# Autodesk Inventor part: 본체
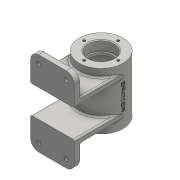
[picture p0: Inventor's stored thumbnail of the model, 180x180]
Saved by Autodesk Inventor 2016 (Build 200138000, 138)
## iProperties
Created: 2017-02
Part Number: 본체
Material: 일반
Document SubType Name: Modeling
Designer: CAMTIC
Density: 1 g/cm^3
Appearance: 기본값
Author: CAMTIC
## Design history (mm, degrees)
sketch "스케치1"
  geometry: L1 (27, 52)-(-27, 52); L2 (-27, -52)-(27, -52); L3 (27, -17)-(-27, -17); L4 (27, 17)-(-27, 17); L5 (-27, 52)-(-27, 17); L6 (-27, -17)-(-27, -52); L7 (27, -52)-(27, -17); L8 (27, 17)-(27, 52); 1 further point
  constraints: 16 end point, 5 parallel, 2 perpendicular, 1 horizontal
  dimensions: "d0" = 54 distance of L2.start L2.end; "d1" = 104 distance of L1.end L2.start
extrude "돌출1" new body sketch "스케치1" distance "d4" = 8; taper "d5" = 0 deg
sketch "스케치2"
  geometry: L1 (0, 0)-(0, 60); C1 r 27 at (0, 60)
  constraints: 2 end point, 1 centre point, 1 coincident, 1 vertical
  dimensions: "d6" = 60 distance of L1.start L1.end; "d7" = 54 diameter of C1
extrude "돌출2" join sketch "스케치2" stored distance "d8" = 70; taper "d9" = 0 deg
sketch "스케치3"
  geometry: L1 (0, 0)-(60, 0); L2 (33, -35)-(87, -35) reference; L3 (60, -35)-(60, 35); L4 (60, -35)-(76, -35); L5 (76, -35)-(76, -23); L6 (76, -23)-(74, -23); L7 (74, -23)-(74, -20); L8 (74, -20)-(82, -20); L9 (87, -35)-(87, 35) reference; L10 (82, -20)-(82, 20); L11 (82, 20)-(74, 20); L12 (74, 20)-(74, 23); L13 (74, 23)-(76, 23); L14 (76, 23)-(76, 35); L15 (87, 35)-(33, 35) reference; L16 (76, 35)-(60, 35)
  constraints: 26 end point, 6 perpendicular, 3 horizontal, 2 point on line, 2 vertical, 1 collinear, 1 midpoint
  dimensions: "d10" = 60 distance of L1.start L1.end; "d11" = 16 distance of L3.start L4.end; "d12" = 12 distance of L4.end L5.end; "d13" = 2 distance of L5.end L6.end; "d14" = 3 distance of L6.end L7.end; "d15" = 8 distance of L7.end L8.end; "d16" = 40 distance of L8.end L10.end; "d17" = 8 distance of L10.end L11.end; "d18" = 3 distance of L11.end L12.end; "d19" = 2 distance of L12.end L13.end
revolve "회전1" sketch "스케치3" stored, may be unused: angle "d20" = 90 deg
node "작업 평면1"
sketch "스케치4"
  geometry: L1 (27, 35)-(-27, 35) reference; L2 (0, 35)-(0, 10); C1 r 5 at (0, 10); 1 further point
  constraints: 2 end point, 1 centre point, 1 coincident, 1 midpoint, 1 vertical
  dimensions: "d22" = 25 distance of L2.start L2.end; "d23" = 10 diameter of C1
extrude "돌출3" join sketch "스케치4" stored distance "d24" = 0; taper "d25" = 0 deg
sketch "스케치5"
  geometry: L1 (-27, 17)-(27, 17) reference; L2 (-27, 17)-(-27, 25); L3 (-27, 25)-(27, 25); L4 (27, 25)-(27, 17); L5 (27, 17)-(-27, 17); L6 (27, -17)-(27, -25); L7 (27, -52)-(27, -17) reference; L8 (27, -25)-(-27, -25); L9 (27, -17)-(-27, -17) reference; L10 (-27, -25)-(-27, -17); L11 (-27, -17)-(27, -17); 1 further point
  constraints: 16 end point, 5 perpendicular, 1 collinear, 1 point on line, 1 vertical
  dimensions: "d26" = 8 distance of L1.start L2.end; "d27" = 8 distance of L6.start L6.end
extrude "돌출4" join sketch "스케치5" stored distance "d28" = 70; taper "d29" = 0 deg
sketch "스케치6"
  geometry: A1 r 21 centre (0, 0) between (0, 21) and (21, 0); 3 further points
  constraints: 4 point on circle, 1 centre point
  dimensions: "d30" = 42 diameter of A1
hole "구멍1" sketch "스케치6" at (0, 21), (21, 0), (0, -21), (-21, 0) diameter "d31" = 3.242; stored, may be unused: countersink angle "d35" = 90 deg, drill point angle "d37" = 118 deg; dims "d32" = 8, "d33" = 4, "d34" = 2, "d36" = 10
sketch "스케치7" dims "d38" = 42
  geometry: C1 r 1.621 at (0, 21) reference; C2 r 1.621 at (21, 0) reference; C3 r 1.621 at (0, -21) reference; 7 further points
  constraints: 4 coincident, 1 horizontal alignment, 2 other
hole "구멍2" sketch "스케치7" at (0, 21), (21, 0), (0, -21), (-21, 0) diameter "d39" = 3.242; stored, may be unused: countersink angle "d43" = 90 deg, drill point angle "d45" = 118 deg; dims "d40" = 8, "d41" = 4, "d42" = 2, "d44" = 10
sketch "스케치8"
  geometry: 2 further points
hole "구멍3" sketch "스케치8" at (0, 0) diameter "d46" = 5.188; stored, may be unused: countersink angle "d50" = 90 deg, drill point angle "d52" = 118 deg; dims "d47" = 12, "d48" = 4, "d49" = 2, "d51" = 16
node "작업 평면2"
sketch "스케치10"
  geometry: L1 (0, 0)-(-16.339, -25.16); L2 (0, 0)-(30, 0); 2 further points
  constraints: 4 end point, 1 equal length, 1 horizontal
  dimensions: "d89" = 30 distance of L1.start L1.end; "d90" = 123 deg angle of L1 L2
sketch "스케치13"
  geometry: L1 (27, 52)-(-27, 52) reference; L2 (0, 52)-(0, -52); L3 (-27, -52)-(27, -52) reference; L4 (17, 52)-(17, -52); L5 (-17, 52)-(-17, -52); L6 (-27, 0)-(27, 0); L7 (-27, 42)-(27, 42); L8 (-27, -42)-(27, -42); L9 (-12.5, 39.402)-(-17, 36.804); L10 (-17, 36.804)-(-21.5, 39.402); L11 (-21.5, 39.402)-(-21.5, 44.598); L12 (-21.5, 44.598)-(-17, 47.196); L13 (-17, 47.196)-(-12.5, 44.598); L14 (-12.5, 44.598)-(-12.5, 39.402); L15 (21.5, 39.402)-(17, 36.804); L16 (17, 36.804)-(12.5, 39.402); L17 (12.5, 39.402)-(12.5, 44.598); L18 (12.5, 44.598)-(17, 47.196); L19 (17, 47.196)-(21.5, 44.598); L20 (21.5, 44.598)-(21.5, 39.402); L21 (21.5, -44.598)-(17, -47.196); L22 (17, -47.196)-(12.5, -44.598); L23 (12.5, -44.598)-(12.5, -39.402); L24 (12.5, -39.402)-(17, -36.804); L25 (17, -36.804)-(21.5, -39.402); L26 (21.5, -39.402)-(21.5, -44.598); L27 (-12.5, -44.598)-(-17, -47.196); L28 (-17, -47.196)-(-21.5, -44.598); L29 (-21.5, -44.598)-(-21.5, -39.402); L30 (-21.5, -39.402)-(-17, -36.804); L31 (-17, -36.804)-(-12.5, -39.402); L32 (-12.5, -39.402)-(-12.5, -44.598); C1 r 4.5 at (-17, 42); C2 r 4.5 at (17, 42); C3 r 4.5 at (17, -42); C4 r 4.5 at (-17, -42); 9 further points
  constraints: 60 end point, 6 midpoint, 5 point on line, 4 centre point, 4 parallel, 3 coincident, 1 horizontal, 52 other
  dimensions: "d68" = 17 distance between parallel lines of L2 L4; "d69" = 17 distance between parallel lines of L2 L5; "d70" = 42 distance between parallel lines of L6 L7; "d71" = 42 distance between parallel lines of L6 L8; "d84" = 9 diameter of C1; "d85" = 9 diameter of C2; "d86" = 9 diameter of C3; "d87" = 9 diameter of C4
extrude "돌출6" cut sketch "스케치13" distance "d76" = 3; taper "d77" = 0 deg
sketch "스케치15"
  geometry: C1 r 2.5 at (-17, 42); C2 r 2.5 at (17, 42); C3 r 2.5 at (17, -42); C4 r 2.5 at (-17, -42); 1 further point
  constraints: 4 centre point
  dimensions: "d78" = 5 diameter of C1; "d79" = 5 diameter of C2; "d80" = 5 diameter of C3; "d81" = 5 diameter of C4
extrude "돌출7" cut sketch "스케치15" stored distance "d82" = 3; taper "d83" = 0 deg
node "작업 평면4"
node "작업 평면5"
sketch "스케치17"
  geometry: C1 r 6 at (0, 0); 1 further point
  constraints: 1 centre point
  dimensions: "d91" = 12 diameter of C1
extrude "돌출8" join sketch "스케치17" stored distance "d92" = 3; taper "d93" = 0 deg
sketch "스케치18"
  geometry: 2 further points
hole "구멍5" sketch "스케치18" at (0, 0) diameter "d94" = 5.188; stored, may be unused: countersink angle "d98" = 90 deg, drill point angle "d100" = 118 deg; dims "d95" = 12, "d96" = 4, "d97" = 2, "d99" = 16
sketch "스케치19"
  geometry: L1 (87, 35)-(33, 35) reference; L2 (87, 35)-(87, 0); L3 (87, -35)-(87, 35) reference; L4 (87, 0)-(60, 0); L5 (62.402, 16.049)-(62.402, -17.134); L6 (62.402, -17.134)-(57.598, -17.134); L7 (57.598, -17.134)-(57.598, 16.049); L8 (57.598, 16.049)-(62.402, 16.049); 1 further point
  constraints: 4 end point, 1 midpoint, 1 perpendicular, 2 other
  dimensions: "d101" = 35 distance of L1.start L2.end (derived); "d102" = 27 distance of L2.end L4.end
feature "엠보싱1" sketch "스케치19" dims "d0" = 54, "d1" = 104, "d11" = 16, "d12" = 12, "d13" = 2, "d14" = 3, "d15" = 8, "d16" = 40, "d17" = 8, "d18" = 3, "d19" = 2, "d103" = 0.5, "d104" = 0
fillet "모깎기1" dims "d105" = 2
fillet "모깎기2" dims "d106" = 10
fillet "모깎기3" dims "d107" = 3
fillet "모깎기4" dims "d108" = 0.3
chamfer "모따기1" distance "d109" = 1; stored, may be unused: second distance "d110" = 2, angle "d111" = 45 deg
chamfer "모따기2" distance "d112" = 1; stored, may be unused: second distance "d113" = 2, angle "d114" = 45 deg
node "솔리드1"
other parameters: "d21" = 92, "d55" = -35
